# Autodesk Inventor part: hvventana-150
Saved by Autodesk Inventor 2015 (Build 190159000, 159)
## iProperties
Created: 2020-08
Part Number: hvventana-150
Checked By: TraceParts S.A.
Material: Generic
Catalog Web Link: www.traceparts.com
Document SubType Name: Modeling
Designer: TraceParts
Density: 1 g/cm^3
Appearance: Default
Company: TraceParts S.A.
Author: TraceParts
REFERENCE: HVVENTANA-150
DESIGN: HVVENTANA-150
SUPPLIER: Soler & Palau
TraceParts.PartNumber: 10-04022019-080750
TraceParts.PartTitle: HV-STYLVENT
TraceParts.InstanceId: 10-04022019-0807501W1B7209E48T0VWBHZQ8JIUVW
TraceParts.PartStatus: Published
TraceParts.PartVersion: 1.0.1
TRACEPARTS: TRACEPARTS
TraceParts.PartLanguage: en
TraceParts.ClassPath: SOLER_PALAU:10-04022019-080750
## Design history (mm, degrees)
feature "hvventana-150"
body "Solid1"
